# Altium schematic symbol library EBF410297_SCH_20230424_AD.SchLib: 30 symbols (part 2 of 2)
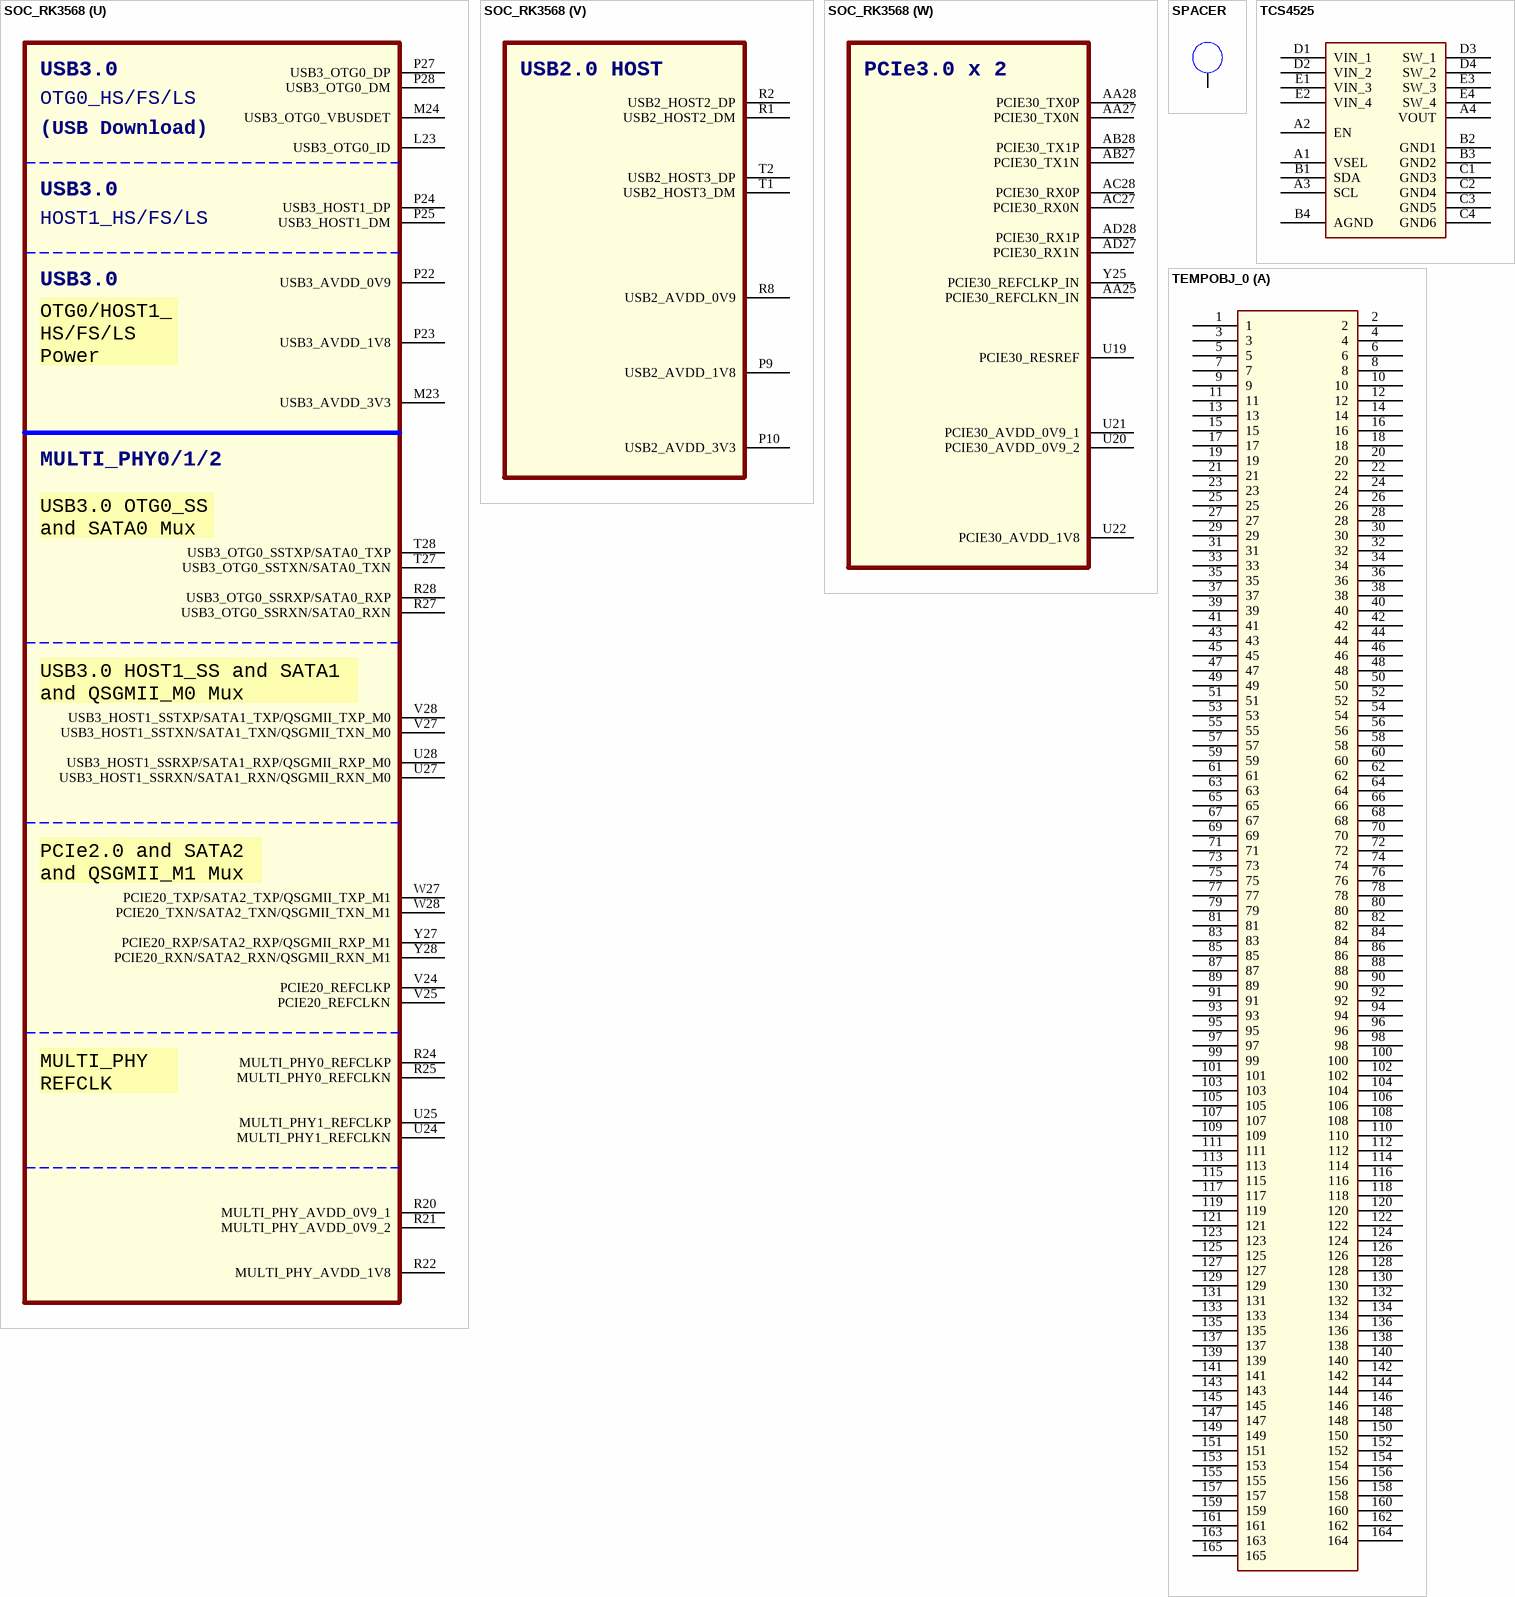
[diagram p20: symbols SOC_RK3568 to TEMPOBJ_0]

## SOC_RK3568
designator U?
SWAP_INFO: (S1+S2+S3+S4+S5+S6+S7+S8+S9+S10+S11+S12+S13+S14+S15+S16+S17+S18+S19+S20+S21+S22+S23); SPLIT_INST: TRUE
footprint BGA636_1
part A pins: J15 VDD_CPU_1, K15 VDD_CPU_2, K16 VDD_CPU_3, K17 VDD_CPU_4, K18 VDD_CPU_5, L12 VDD_LOGIC_1, L15 VDD_CPU_6, L16 VDD_CPU_7, L17 VDD_CPU_8, L18 VDD_CPU_9, M12 VDD_LOGIC_2, M15 VDD_CPU_COM, M17 VDD_CPU_10, M19 VDD_NPU_1, N13 VDD_LOGIC_3, N16 VDD_LOGIC_4, N19 VDD_NPU_2, P13 VDD_LOGIC_5, P16 VDD_LOGIC_6, P18 VDD_NPU_3, P19 VDD_NPU_4, P20 VDD_NPU_5, R12 VDD_LOGIC_7, R13 VDD_GPU_1, R16 VDD_LOGIC_8, T12 VDD_LOGIC_9, T13 VDD_GPU_2, T16 VDD_LOGIC_10, U11 VDD_GPU_3, U12 VDD_GPU_4, U13 VDD_GPU_5
part B pins: A1 VSS_1, A3 VSS_2, A6 VSS_3, A10 VSS_4, A14 VSS_5, A18 VSS_6, A28 VSS_7, B5 VSS_8, B9 VSS_9, B12 VSS_10, B16 VSS_11, B23 VSS_12, B26 VSS_13, C3 VSS_14, C6 VSS_15, C8 VSS_16, C9 VSS_17, C11 VSS_18, C12 VSS_19, C14 VSS_20, C15 VSS_21, C17 VSS_22, C18 VSS_23, C25 VSS_24, D2 VSS_25, D3 VSS_26, D11 VSS_27, D28 VSS_28, E3 VSS_29, E7 VSS_30, F1 VSS_31, F3 VSS_32, F9 VSS_33, F12 VSS_34, F14 VSS_35, F15 VSS_36, F17 VSS_37, G5 VSS_38, G6 VSS_39, G8 VSS_40, G9 VSS_41, G11 VSS_42, G12 VSS_43, G14 VSS_44, G15 VSS_45, G17 VSS_46, G18 VSS_47, G24 VSS_48, H2 VSS_49, H3 VSS_50, H6 VSS_51, J3 VSS_52, J5 VSS_53, J17 VSS_54, J18 VSS_55, J20 VSS_56, J22 VSS_57, J26 VSS_58, K1 VSS_59, K11 VSS_60, K12 VSS_61, K13 VSS_62, K14 VSS_63, K19 VSS_64, L3 VSS_65
part C pins: L5 VSS_66, L8 VSS_67, L11 VSS_68, L13 VSS_69, L14 VSS_70, L19 VSS_71, L20 VSS_72, L21 VSS_73, M2 VSS_74, M3 VSS_75, M6 VSS_76, M8 VSS_77, M11 VSS_78, M13 VSS_79, M14 VSS_80, M16 VSS_81, M18 VSS_82, N1 VSS_83, N12 VSS_84, N14 VSS_85, N15 VSS_86, N17 VSS_87, N18 VSS_88, P3 VSS_89, P6 VSS_90, P12 VSS_91, P14 VSS_92, P15 VSS_93, P17 VSS_94, R3 VSS_95, R6 VSS_96, R10 VSS_97, R11 VSS_98, R14 VSS_99, R15 VSS_100, R17 VSS_101, R18 VSS_102, R19 VSS_103, T10 VSS_104, T11 VSS_105, T14 VSS_106, T15 VSS_107, T17 VSS_108, T18 VSS_109, T19 VSS_110, U1 VSS_111, U6 VSS_112, U7 VSS_113, U8 VSS_114, U10 VSS_115, U14 VSS_116, U15 VSS_117, U16 VSS_118, U17 VSS_119, U18 VSS_120, V3 VSS_121, V8 VSS_122, V9 VSS_123, V13 VSS_124, W10 VSS_125, W11 VSS_126, W12 VSS_127, W13 VSS_128, Y8 VSS_129, Y9 VSS_130
part D pins: AA4 VSS_133, AA9 VSS_134, AA23 VSS_135, AB2 VSS_136, AB6 VSS_137, AD3 VSS_138, AE6 VSS_139, AE21 VSS_140, AF3 VSS_141, AF26 VSS_142, AG5 VSS_143, AH1 VSS_144, AH8 VSS_145, AH28 VSS_146, Y11 VSS_131, Y12 VSS_132
part E pins: AA12 AVSS_24, AA14 AVSS_25, AA15 AVSS_26, AA17 AVSS_27, AA24 AVSS_28, AA26 AVSS_29, AB11 AVSS_30, AB12 AVSS_31, AB14 AVSS_32, AB15 AVSS_33, AB17 AVSS_34, AC9 AVSS_35, AC11 AVSS_36, AC12 AVSS_37, AC15 AVSS_38, AC18 AVSS_39, AC25 AVSS_40, AC26 AVSS_41, AD26 AVSS_42, AE14 AVSS_43, AE17 AVSS_44, AE20 AVSS_45, AE27 AVSS_46, AE28 AVSS_47, AF9 AVSS_48, AF11 AVSS_49, AF12 AVSS_50, AF14 AVSS_51, AF15 AVSS_52, AF17 AVSS_53, AF18 AVSS_54, AF20 AVSS_55, AF21 AVSS_56, AG18 AVSS_57, AH18 AVSS_58, AH23 AVSS_59, J27 AVSS_1, L24 AVSS_2, L26 AVSS_3, M21 AVSS_4, M26 AVSS_5, N28 AVSS_6, P21 AVSS_7, P26 AVSS_8, R23 AVSS_9, R26 AVSS_10, U23 AVSS_11, U26 AVSS_12, V14 AVSS_13, V15 AVSS_14, V16 AVSS_15, V22 AVSS_16, V23 AVSS_17, V26 AVSS_18, W17 AVSS_19, Y18 AVSS_20, Y23 AVSS_21, Y24 AVSS_22, Y26 AVSS_23
part F pins: A2 AC25, A4 AC24, A5 AC9, A7 AC6, A8 AC7, A9 DDR_DQ1_B, A11 DDR_DQS0P_B, A12 DDR_DQ4_B, A13 DDR_DQ13_B, A15 DDR_DQS1N_B, A16 DDR_DQ8_B, A17 DDR_DQ10_B, B1 AC2, B2 AC26, B3 AC22, B4 AC23, B6 AC0, B7 AC5, B8 AC13, B10 DDR_DQ0_B, B11 DDR_DQS0N_B, B13 DDR_DQ12_B, B14 DDR_DQ15_B, B15 DDR_DQS1P_B, B17 DDR_DQ9_B, B18 DDR_DQ11_B, C1 AC8, C2 AC11, C4 AC12, C5 AC14, D1 DDR_DQ3_A, D5 AC16, D6 AC10, D8 AC28, D9 AC4, D12 DDR_DQ2_B, D14 DDR_DM0_B, D15 DDR_DQ5_B, D17 DDR_DQ14_B, E1 DDR_DQ1_A, E2 DDR_DQ2_A, E4 AC15, E6 AC17, E8 AC27, E9 AC19, E11 AC18, E12 DDR_DQ3_B, E14 DDR_DQ7_B, E15 DDR_DQ6_B, E17 DDR_DM1_B, F2 DDR_DQ0_A, F4 AC3, F5 AC1, F7 AC21, F8 AC20, F11 AC29, G1 DDR_DQS0P_A, G2 DDR_DQS0N_A, H1 DDR_DQ6_A, H4 DDR_DQ7_A, H5 DDR_DM0_A, H7 DDR_RZQ, H9 DDRPHY_VDDQ_1, H11 DDRPHY_VDDQ_2, H12 DDRPHY_VDDQ_3, H14 DDRPHY_VDDQ_4, H15 DDRPHY_VDDQ_5, J1 DDR_DQ4_A, J2 DDR_DQ5_A, J4 DDR_DM1_A, J6 DDR_DQ13_A, J7 DDR_DQ14_A, J8 DDR_AVSS, J9 DDRPHY_VDDQ_6, J11 DDRPHY_VDDQL_1, J12 DDRPHY_VDDQL_2, J14 DDRPHY_VDDQL_3, K2 DDR_DQ12_A, K10 DDRPHY_VDDQL_4, L1 DDR_DQS1N_A, L2 DDR_DQS1P_A, L4 DDR_DQ15_A, L6 DDR_DQ11_A, L7 DDR_DQ10_A, L9 DDRPHY_VDDQ_7, L10 DDRPHY_VDDQL_5, M1 DDR_DQ8_A, M4 DDR_ECC_DQ1, M5 DDR_ECC_DQ2, M7 DDR_ECC_DQ4, M9 DDRPHY_VDDQ_8, M10 DDRPHY_VDDQL_6, N2 DDR_DQ9_A, P1 DDR_ECC_DQS_N, P2 DDR_ECC_DQS_P, P4 DDR_ECC_DQ6, P5 DDR_ECC_DQ0, P7 DDR_ECC_DM, P8 DDR_VREFOUT, R4 DDR_ECC_DQ7, R5 DDR_ECC_DQ3, R7 DDR_ECC_DQ5
part G pins: AA20 GPIO0_B6_u, AA22 GPIO0_A3_u, AB20 GPIO0_B4_u, AB21 GPIO0_B2_u, AB23 GPIO0_D4_d, AB24 TVSS, AC20 GPIO0_D0_u, AC21 GPIO0_C5_d, AC22 GPIO0_B5_u, AC24 GPIO0_D6_d, AD20 GPIO0_C6_d, AD21 GPIO0_C4_d, AD22 GPIO0_C0_d, AD23 GPIO0_B0_u, AD25 GPIO0_D5_d, AE23 GPIO0_C3_d, AE24 GPIO0_A6_d, AE26 GPIO0_D3_d, AF23 GPIO0_C1_d, AF24 GPIO0_B1_u, AF25 GPIO0_A5_d, AF27 XOUT24M, AF28 XIN24M, AG23 GPIO0_C2_d, AG24 GPIO0_B3_u, AG25 GPIO0_A7_u, AG26 GPIO0_A1_z, AG27 GPIO0_A0_d, AG28 GPIO0_A2_d, AH24 GPIO0_D1_u, AH25 GPIO0_C7_d, AH26 GPIO0_B7_d, AH27 NPOR_u, N10 SYSPLL_AVDD_1V8, N11 SYSPLL_AVSS, P11 SYSPLL_AVDD_0V9, V19 PMU_VDD_LOGIC_0V9, V20 PMUPLL_AVSS, V21 PMUPLL_AVDD_0V9, W19 PMUIO2, Y20 PMUIO1, Y21 PMUPLL_AVDD_1V8, Y22 GPIO0_A4_u
part H pins: A19 GPIO1_A2_d, A20 GPIO1_A5_d, A21 GPIO1_B2_d, B19 GPIO1_A3_d, B20 GPIO1_A7_d, B21 GPIO1_B3_d, C20 GPIO1_A6_d, D18 GPIO1_A0_u, D20 GPIO1_B0_d, E18 GPIO1_A1_u, E20 GPIO1_B1_d, F18 GPIO1_A4_d, H17 VCCIO1
part I pins: A22 GPIO1_D0_d, A23 GPIO1_C5_d, A24 GPIO1_B4_u, A25 GPIO1_C0_u, A26 GPIO1_C6_d, A27 GPIO1_D4_u, B22 GPIO1_C4_u, B24 GPIO1_B6_u, B25 GPIO1_C3_u, C21 GPIO1_B5_u, C23 GPIO1_D3_u, C24 GPIO1_D1_u, D21 GPIO1_B7_u, D23 GPIO1_D2_u, E21 GPIO1_C1_u, E22 GPIO1_C2_u, F20 GPIO1_C7_d, H18 VCCIO2
part J pins: H26 GPIO1_D7_u, H27 GPIO2_A1_u, H28 GPIO2_A2_d, J23 GPIO2_A0_u, J24 GPIO1_D6_u, J25 GPIO1_D5_u, L22 VCCIO3
part K pins: B28 GPIO2_A5_u, C27 GPIO2_A6_u, C28 GPIO2_A7_u, D26 GPIO2_B1_d, D27 GPIO2_B0_d, E25 GPIO2_B2_u, E26 GPIO2_C6_d, E27 GPIO2_A3_u, E28 GPIO2_A4_u, F24 GPIO2_C0_d, F25 GPIO2_C2_d, F26 GPIO2_C5_d, F27 GPIO2_B6_u, F28 GPIO2_B3_u, G23 GPIO2_C1_d, G27 GPIO2_B4_u, G28 GPIO2_B5_u, H23 GPIO2_C4_d, H24 GPIO2_C3_d, H25 GPIO2_B7_d, J21 VCCIO4
part L pins: AA7 GPIO3_C2_d, AB8 GPIO3_A1_d, AC2 GPIO3_C5_d, AC3 GPIO3_C4_d, AC4 GPIO3_C3_d, AC7 GPIO2_D3_d, AC8 GPIO2_D2_d, AD1 GPIO3_C1_d, AD2 GPIO3_C0_d, AD4 GPIO3_B7_d, AD6 GPIO2_D6_d, AD7 GPIO2_D1_d, AE1 GPIO3_B4_d, AE2 GPIO3_B5_d, AE3 GPIO3_B6_d, AE5 GPIO3_A2_d, AF1 GPIO3_B3_d, AF2 GPIO3_B2_d, AF4 GPIO3_A4_d, AF5 GPIO2_D4_d, AF6 GPIO2_D5_d, AG1 GPIO3_B1_d, AG2 GPIO3_B0_d, AG3 GPIO3_A6_d, AG4 GPIO3_A3_d, AG6 GPIO2_D0_d, AH2 GPIO3_A7_d, AH3 GPIO3_A5_d, AH4 GPIO3_A0_d, AH5 GPIO2_D7_d, V10 VCCIO5_1, V11 VCCIO5_2
part M pins: AA1 GPIO3_D4_d, AA2 GPIO4_A1_d, AA3 GPIO4_A0_d, AA5 GPIO3_D5_d, AA6 GPIO3_C7_d, AB1 GPIO3_D1_d, AB5 GPIO3_D0_d, AC1 GPIO3_D3_d, AC5 GPIO3_C6_d, R9 VCCIO6_1, U2 GPIO4_C1_d, U3 GPIO4_C0_d, U4 GPIO4_B7_d, U5 GPIO4_B6_d, U9 VCCIO6_2, V1 GPIO4_B3_d, V2 GPIO4_B1_d, V4 GPIO4_B2_d, V5 GPIO4_B5_d, V6 GPIO4_B4_d, V7 GPIO4_B0_d, W1 GPIO4_A7_d, W2 GPIO4_A6_d, Y1 GPIO4_A5_d, Y2 GPIO4_A4_d, Y3 GPIO4_A3_d, Y4 GPIO4_A2_d, Y5 GPIO3_D7_d, Y6 GPIO3_D6_d, Y7 GPIO3_D2_d
part N pins: AA11 GPIO4_C3_d, AB9 GPIO4_D2_d, AD8 GPIO4_C5_d, AE8 GPIO4_C6_d, AF8 GPIO4_C2_d, AG7 GPIO4_D0_u, AG8 GPIO4_C7_u, AH6 GPIO4_D1_u, AH7 GPIO4_C4_d, V12 VCCIO7
part O pins: B27 SARADC_VIN0, C26 SARADC_VIN1, D24 SARADC_VIN2, E23 SARADC_VIN3, F21 SARADC_VIN7, F22 SARADC_VIN5, G20 SARADC_VIN6, G21 SARADC_VIN4, H20 OTP_VCC18, H22 SARADC_AVDD_1V8
part P pins: AD9 MIPI_CSI_RX_D3P, AD11 MIPI_CSI_RX_D2N, AE9 MIPI_CSI_RX_D3N, AE11 MIPI_CSI_RX_D2P, AG9 MIPI_CSI_RX_CLK1P, AG10 MIPI_CSI_RX_CLK0P, AG11 MIPI_CSI_RX_D1P, AG12 MIPI_CSI_RX_D0P, AH9 MIPI_CSI_RX_CLK1N, AH10 MIPI_CSI_RX_CLK0N, AH11 MIPI_CSI_RX_D1N, AH12 MIPI_CSI_RX_D0N, W14 MIPI_CSI_RX_AVDD_0V9, Y14 MIPI_CSI_RX_AVDD_1V8
part Q pins: AA18 HDMI_TX_REXT, AB18 HDMI_TX_HPDIN, AG19 HDMI_TX_CLKN, AG20 HDMI_TX_D0P, AG21 HDMI_TX_D1P, AG22 HDMI_TX_D2P, AH19 HDMI_TX_CLKP, AH20 HDMI_TX_D0N, AH21 HDMI_TX_D1N, AH22 HDMI_TX_D2N, V17 HDMI_TX_AVDD_0V9_1, V18 HDMI_TX_AVDD_0V9_2, W18 HDMI_TX_AVDD_1V8
part R pins: AG13 MIPI_DSI_TX0_D3N/LVDS_TX0_D3N, AG14 MIPI_DSI_TX0_D2N/LVDS_TX0_D2N, AG15 MIPI_DSI_TX0_CLKN/LVDS_TX0_CLKN, AG16 MIPI_DSI_TX0_D1N/LVDS_TX0_D1N, AG17 MIPI_DSI_TX0_D0N/LVDS_TX0_D0N, AH13 MIPI_DSI_TX0_D3P/LVDS_TX0_D3P, AH14 MIPI_DSI_TX0_D2P/LVDS_TX0_D2P, AH15 MIPI_DSI_TX0_CLKP/LVDS_TX0_CLKP, AH16 MIPI_DSI_TX0_D1P/LVDS_TX0_D1P, AH17 MIPI_DSI_TX0_D0P/LVDS_TX0_D0P, W16 MIPI_DSI_TX0/LVDS_TX0_AVDD_0V9, Y17 MIPI_DSI_TX0/LVDS_TX0_AVDD_1V8
part S pins: AC14 MIPI_DSI_TX1_D2N, AC17 MIPI_DSI_TX1_D1N, AD12 MIPI_DSI_TX1_D3P, AD14 MIPI_DSI_TX1_D2P, AD15 MIPI_DSI_TX1_CLKP, AD17 MIPI_DSI_TX1_D1P, AD18 MIPI_DSI_TX1_D0P, AE12 MIPI_DSI_TX1_D3N, AE15 MIPI_DSI_TX1_CLKN, AE18 MIPI_DSI_TX1_D0N, W15 MIPI_DSI_TX1_AVDD_0V9, Y15 MIPI_DSI_TX1_AVDD_1V8
part T pins: J28 eDP_TX_D0P, K27 eDP_TX_D0N, K28 eDP_TX_D1P, L25 eDP_TX_AUXP, L27 eDP_TX_D1N, L28 eDP_TX_D2P, M20 eDP_TX_AVDD_0V9, M22 eDP_TX_AVDD_1V8, M25 eDP_TX_AUXN, M27 eDP_TX_D2N, M28 eDP_TX_D3P, N27 eDP_TX_D3N
part U pins: L23 USB3_OTG0_ID, M23 USB3_AVDD_3V3, M24 USB3_OTG0_VBUSDET, P22 USB3_AVDD_0V9, P23 USB3_AVDD_1V8, P24 USB3_HOST1_DP, P25 USB3_HOST1_DM, P27 USB3_OTG0_DP, P28 USB3_OTG0_DM, R20 MULTI_PHY_AVDD_0V9_1, R21 MULTI_PHY_AVDD_0V9_2, R22 MULTI_PHY_AVDD_1V8, R24 MULTI_PHY0_REFCLKP, R25 MULTI_PHY0_REFCLKN, R27 USB3_OTG0_SSRXN/SATA0_RXN, R28 USB3_OTG0_SSRXP/SATA0_RXP, T27 USB3_OTG0_SSTXN/SATA0_TXN, T28 USB3_OTG0_SSTXP/SATA0_TXP, U24 MULTI_PHY1_REFCLKN, U25 MULTI_PHY1_REFCLKP, U27 USB3_HOST1_SSRXN/SATA1_RXN/QSGMII_RXN_M0, U28 USB3_HOST1_SSRXP/SATA1_RXP/QSGMII_RXP_M0, V24 PCIE20_REFCLKP, V25 PCIE20_REFCLKN, V27 USB3_HOST1_SSTXN/SATA1_TXN/QSGMII_TXN_M0, V28 USB3_HOST1_SSTXP/SATA1_TXP/QSGMII_TXP_M0, W27 PCIE20_TXP/SATA2_TXP/QSGMII_TXP_M1, W28 PCIE20_TXN/SATA2_TXN/QSGMII_TXN_M1, Y27 PCIE20_RXP/SATA2_RXP/QSGMII_RXP_M1, Y28 PCIE20_RXN/SATA2_RXN/QSGMII_RXN_M1
part V pins: P9 USB2_AVDD_1V8, P10 USB2_AVDD_3V3, R1 USB2_HOST2_DM, R2 USB2_HOST2_DP, R8 USB2_AVDD_0V9, T1 USB2_HOST3_DM, T2 USB2_HOST3_DP
part W pins: AA25 PCIE30_REFCLKN_IN, AA27 PCIE30_TX0N, AA28 PCIE30_TX0P, AB27 PCIE30_TX1N, AB28 PCIE30_TX1P, AC27 PCIE30_RX0N, AC28 PCIE30_RX0P, AD27 PCIE30_RX1N, AD28 PCIE30_RX1P, U19 PCIE30_RESREF, U20 PCIE30_AVDD_0V9_2, U21 PCIE30_AVDD_0V9_1, U22 PCIE30_AVDD_1V8, Y25 PCIE30_REFCLKP_IN

## SPACER
designator SS?
CLASS: IC
pins: 1 NC_1

## TCS4525
designator U?
footprint WLCSP-20
pins: A1 VSEL, A2 EN, A3 SCL, A4 VOUT, B1 SDA, B2 GND1, B3 GND2, B4 AGND, C1 GND3, C2 GND4, C3 GND5, C4 GND6, D1 VIN_1, D2 VIN_2, D3 SW_1, D4 SW_2, E1 VIN_3, E2 VIN_4, E3 SW_3, E4 SW_4

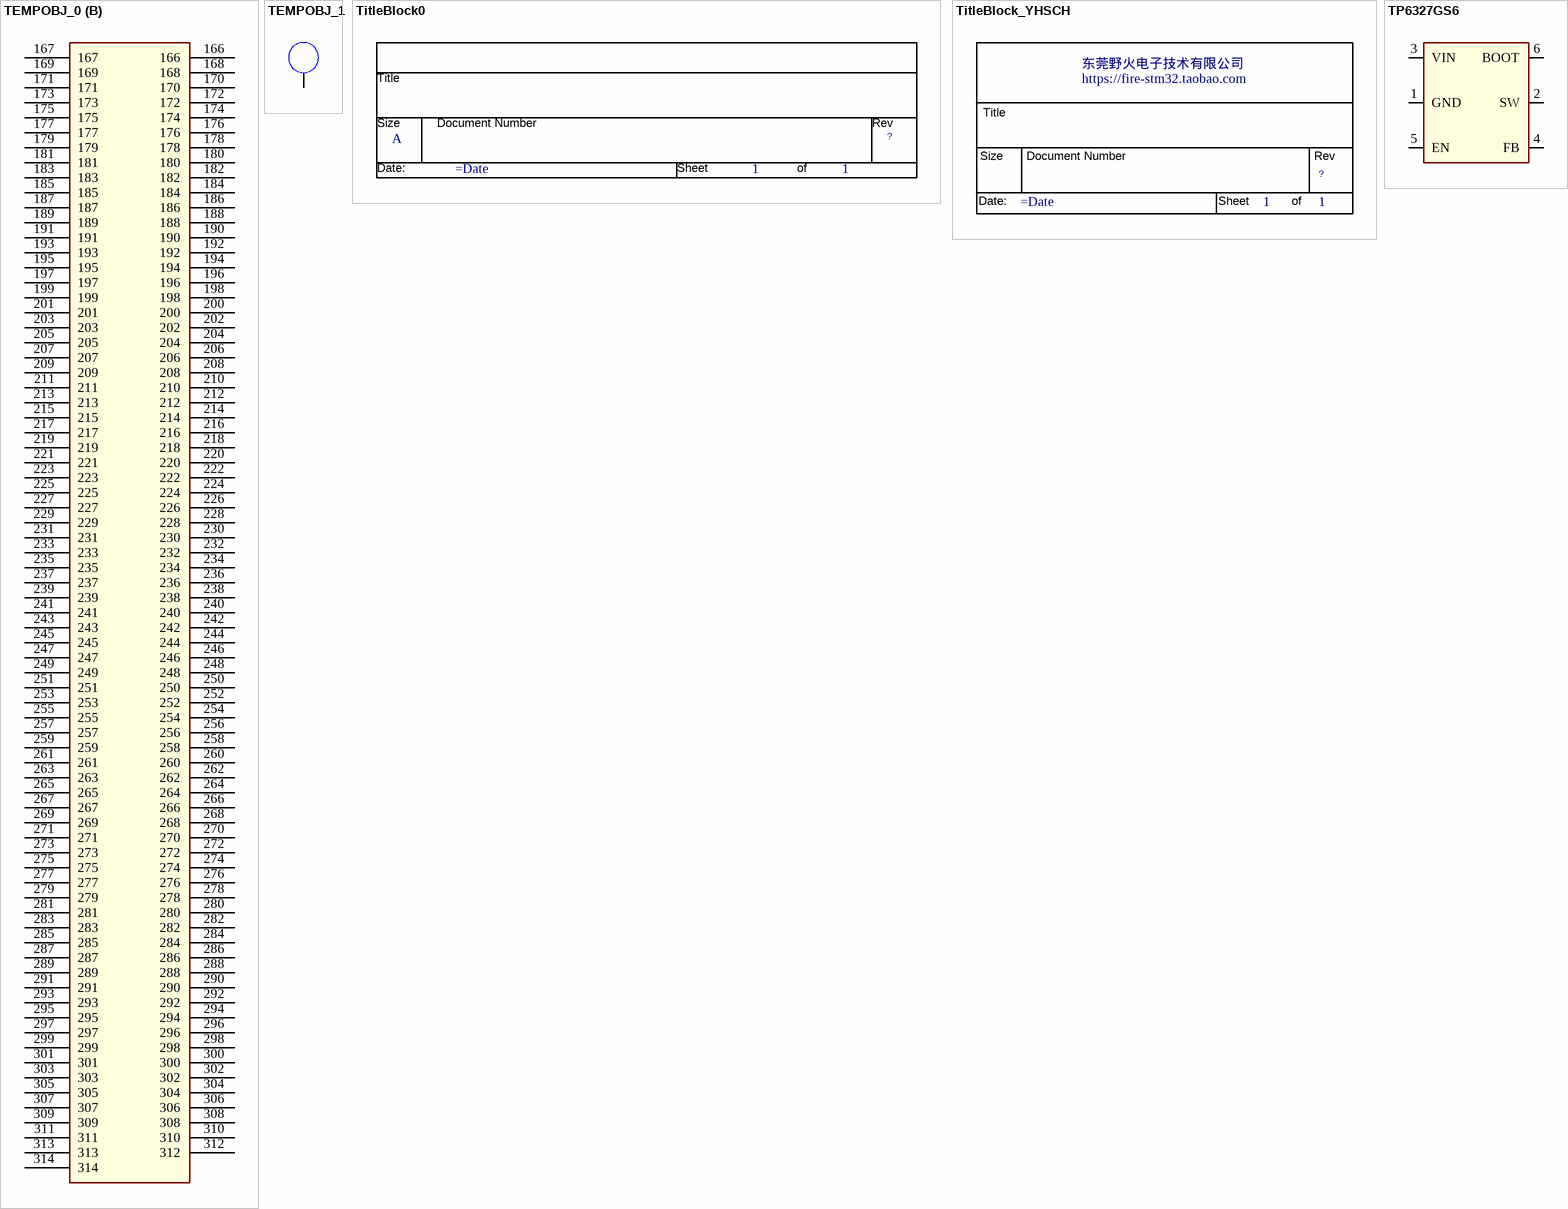
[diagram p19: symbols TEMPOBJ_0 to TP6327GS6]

## TEMPOBJ_0
designator J?
footprint AS0B821-S78B-314PIN
part A pins: 1, 2, 3, 4, 5, 6, 7, 8, 9, 10, 11, 12, 13, 14, 15, 16, 17, 18, 19, 20, 21, 22, 23, 24, 25, 26, 27, 28, 29, 30, 31, 32, 33, 34, 35, 36, 37, 38, 39, 40, 41, 42, 43, 44, 45, 46, 47, 48, 49, 50, 51, 52, 53, 54, 55, 56, 57, 58, 59, 60, 61, 62, 63, 64, 65, 66, 67, 68, 69, 70, 71, 72, 73, 74, 75, 76, 77, 78, 79, 80, 81, 82, 83, 84, 85, 86, 87, 88, 89, 90, 91, 92, 93, 94, 95, 96, 97, 98, 99, 100, 101, 102, 103, 104, 105, 106, 107, 108, 109, 110, 111, 112, 113, 114, 115, 116, 117, 118, 119, 120, 121, 122, 123, 124, 125, 126, 127, 128, 129, 130, 131, 132, 133, 134, 135, 136, 137, 138, 139, 140, 141, 142, 143, 144, 145, 146, 147, 148, 149, 150, 151, 152, 153, 154, 155, 156, 157, 158, 159, 160, 161, 162, 163, 164, 165
part B pins: 166, 167, 168, 169, 170, 171, 172, 173, 174, 175, 176, 177, 178, 179, 180, 181, 182, 183, 184, 185, 186, 187, 188, 189, 190, 191, 192, 193, 194, 195, 196, 197, 198, 199, 200, 201, 202, 203, 204, 205, 206, 207, 208, 209, 210, 211, 212, 213, 214, 215, 216, 217, 218, 219, 220, 221, 222, 223, 224, 225, 226, 227, 228, 229, 230, 231, 232, 233, 234, 235, 236, 237, 238, 239, 240, 241, 242, 243, 244, 245, 246, 247, 248, 249, 250, 251, 252, 253, 254, 255, 256, 257, 258, 259, 260, 261, 262, 263, 264, 265, 266, 267, 268, 269, 270, 271, 272, 273, 274, 275, 276, 277, 278, 279, 280, 281, 282, 283, 284, 285, 286, 287, 288, 289, 290, 291, 292, 293, 294, 295, 296, 297, 298, 299, 300, 301, 302, 303, 304, 305, 306, 307, 308, 309, 310, 311, 312, 313, 314

## TEMPOBJ_1
designator SS?
CLASS: IC
pins: 1 NC_1

## TitleBlock0
designator *  Page Size: A  Page Number: 1  (hidden comment: *)  (graphical)

## TitleBlock_YHSCH
designator *  Page Count: 1  OrgName: 东莞野火电子技术有限公司  (hidden comment: *)  (graphical)

## TP6327GS6
designator U?
pins: 1 GND, 2 SW, 3 VIN, 4 FB, 5 EN, 6 BOOT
